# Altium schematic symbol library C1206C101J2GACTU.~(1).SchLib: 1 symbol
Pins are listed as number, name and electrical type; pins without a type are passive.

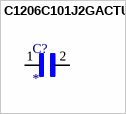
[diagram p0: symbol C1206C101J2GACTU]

## C1206C101J2GACTU
designator C?
CAP CER 100PF 200V C0G/NP0 1206; MP: C1206C101J2GACTU
footprint CAPC3216X88N
pins: 1, 2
